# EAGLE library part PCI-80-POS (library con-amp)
PCI-SLOT 80 Dual Position 0.05 Series Standard Edge Source: http://catalog.tycoelectronics.com .. ENG_CD_650090_AA.tif.tiff
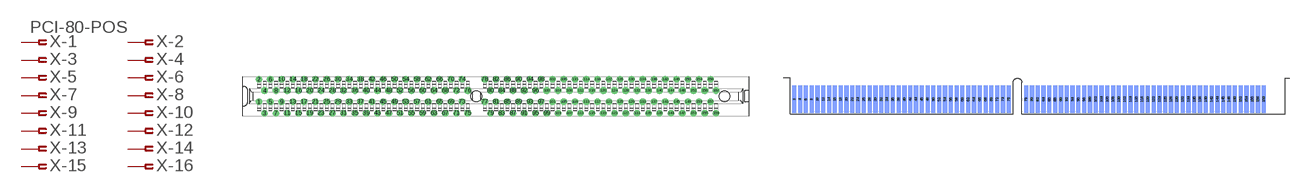
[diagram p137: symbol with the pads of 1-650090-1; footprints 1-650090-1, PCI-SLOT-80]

Designator prefix X; gates -1=PIN-FV -2=PIN-F -3=PIN-F -4=PIN-F -5=PIN-F -6=PIN-F -7=PIN-F -8=PIN-F -9=PIN-F -10=PIN-F -11=PIN-F -12=PIN-F -13=PIN-F -14=PIN-F -15=PIN-F -16=PIN-F -17=PIN-F -18=PIN-F -19=PIN-F -20=PIN-F -21=PIN-F -22=PIN-F -23=PIN-F -24=PIN-F -25=PIN-F -26=PIN-F -27=PIN-F -28=PIN-F -29=PIN-F -30=PIN-F -31=PIN-F -32=PIN-F -33=PIN-F -34=PIN-F -35=PIN-F -36=PIN-F -37=PIN-F -38=PIN-F -39=PIN-F -40=PIN-F -41=PIN-F -42=PIN-F -43=PIN-F -44=PIN-F -45=PIN-F -46=PIN-F -47=PIN-F -48=PIN-F -49=PIN-F -50=PIN-F -51=PIN-F -52=PIN-F -53=PIN-F -54=PIN-F -55=PIN-F -56=PIN-F -57=PIN-F -58=PIN-F -59=PIN-F -60=PIN-F -61=PIN-F -62=PIN-F -63=PIN-F -64=PIN-F -65=PIN-F -66=PIN-F -67=PIN-F -68=PIN-F -69=PIN-F -70=PIN-F -71=PIN-F -72=PIN-F -73=PIN-F -74=PIN-F -75=PIN-F -76=PIN-F -77=PIN-F -78=PIN-F -79=PIN-F -80=PIN-F -81=PIN-F -82=PIN-F -83=PIN-F -84=PIN-F -85=PIN-F -86=PIN-F -87=PIN-F -88=PIN-F -89=PIN-F -90=PIN-F -91=PIN-F -92=PIN-F -93=PIN-F -94=PIN-F -95=PIN-F -96=PIN-F -97=PIN-F -98=PIN-F -99=PIN-F -100=PIN-F -101=PIN-F -102=PIN-F -103=PIN-F -104=PIN-F -105=PIN-F -106=PIN-F -107=PIN-F -108=PIN-F -109=PIN-F -110=PIN-F -111=PIN-F -112=PIN-F -113=PIN-F -114=PIN-F -115=PIN-F -116=PIN-F -117=PIN-F -118=PIN-F -119=PIN-F -120=PIN-F -121=PIN-F -122=PIN-F -123=PIN-F -124=PIN-F -125=PIN-F -126=PIN-F -127=PIN-F -128=PIN-F -129=PIN-F -130=PIN-F -131=PIN-F -132=PIN-F -133=PIN-F -134=PIN-F -135=PIN-F -136=PIN-F -137=PIN-F -138=PIN-F -139=PIN-F -140=PIN-F -141=PIN-F -142=PIN-F -143=PIN-F -144=PIN-F -145=PIN-F -146=PIN-F -147=PIN-F -148=PIN-F -149=PIN-F -150=PIN-F -151=PIN-F -152=PIN-F -153=PIN-F -154=PIN-F -155=PIN-F -156=PIN-F -157=PIN-F -158=PIN-F -159=PIN-F -160=PIN-F

## PCI-80-POS-1-650090-1 (MF: TYCO ELECTRONICS; MPN: 1-650090-1; OC_FARNELL: unknown; OC_NEWARK: 10H3039)  [1-650090-1]
1  -1:1  pas
2  -2:1  pas
3  -3:1  pas
4  -4:1  pas
5  -5:1  pas
6  -6:1  pas
7  -7:1  pas
8  -8:1  pas
9  -9:1  pas
10  -10:1  pas
11  -11:1  pas
12  -12:1  pas
13  -13:1  pas
14  -14:1  pas
15  -15:1  pas
16  -16:1  pas
17  -17:1  pas
18  -18:1  pas
19  -19:1  pas
20  -20:1  pas
21  -21:1  pas
22  -22:1  pas
23  -23:1  pas
24  -24:1  pas
25  -25:1  pas
26  -26:1  pas
27  -27:1  pas
28  -28:1  pas
29  -29:1  pas
30  -30:1  pas
31  -31:1  pas
32  -32:1  pas
33  -33:1  pas
34  -34:1  pas
35  -35:1  pas
36  -36:1  pas
37  -37:1  pas
38  -38:1  pas
39  -39:1  pas
40  -40:1  pas
41  -41:1  pas
42  -42:1  pas
43  -43:1  pas
44  -44:1  pas
45  -45:1  pas
46  -46:1  pas
47  -47:1  pas
48  -48:1  pas
49  -49:1  pas
50  -50:1  pas
51  -51:1  pas
52  -52:1  pas
53  -53:1  pas
54  -54:1  pas
55  -55:1  pas
56  -56:1  pas
57  -57:1  pas
58  -58:1  pas
59  -59:1  pas
60  -60:1  pas
61  -61:1  pas
62  -62:1  pas
63  -63:1  pas
64  -64:1  pas
65  -65:1  pas
66  -66:1  pas
67  -67:1  pas
68  -68:1  pas
69  -69:1  pas
70  -70:1  pas
71  -71:1  pas
72  -72:1  pas
73  -73:1  pas
74  -74:1  pas
75  -75:1  pas
76  -76:1  pas
77  -77:1  pas
78  -78:1  pas
79  -79:1  pas
80  -80:1  pas
81  -81:1  pas
82  -82:1  pas
83  -83:1  pas
84  -84:1  pas
85  -85:1  pas
86  -86:1  pas
87  -87:1  pas
88  -88:1  pas
89  -89:1  pas
90  -90:1  pas
91  -91:1  pas
92  -92:1  pas
93  -93:1  pas
94  -94:1  pas
95  -95:1  pas
96  -96:1  pas
97  -97:1  pas
98  -98:1  pas
99  -99:1  pas
100  -100:1  pas
101  -101:1  pas
102  -102:1  pas
103  -103:1  pas
104  -104:1  pas
105  -105:1  pas
106  -106:1  pas
107  -107:1  pas
108  -108:1  pas
109  -109:1  pas
110  -110:1  pas
111  -111:1  pas
112  -112:1  pas
113  -113:1  pas
114  -114:1  pas
115  -115:1  pas
116  -116:1  pas
117  -117:1  pas
118  -118:1  pas
119  -119:1  pas
120  -120:1  pas
121  -121:1  pas
122  -122:1  pas
123  -123:1  pas
124  -124:1  pas
125  -125:1  pas
126  -126:1  pas
127  -127:1  pas
128  -128:1  pas
129  -129:1  pas
130  -130:1  pas
131  -131:1  pas
132  -132:1  pas
133  -133:1  pas
134  -134:1  pas
135  -135:1  pas
136  -136:1  pas
137  -137:1  pas
138  -138:1  pas
139  -139:1  pas
140  -140:1  pas
141  -141:1  pas
142  -142:1  pas
143  -143:1  pas
144  -144:1  pas
145  -145:1  pas
146  -146:1  pas
147  -147:1  pas
148  -148:1  pas
149  -149:1  pas
150  -150:1  pas
151  -151:1  pas
152  -152:1  pas
153  -153:1  pas
154  -154:1  pas
155  -155:1  pas
156  -156:1  pas
157  -157:1  pas
158  -158:1  pas
159  -159:1  pas
160  -160:1  pas

## PCI-80-POS-SLOT (OC_FARNELL: unknown; OC_NEWARK: unknown)  [PCI-SLOT-80]
Pads as for 1-650090-1

## Footprint 1-650090-1 (pad centres in mm)
PCI Connector 80 Dual Pos. Standard Edge .050 Series PCI Source: http://catalog.tycoelectronics.com .. ENG_CD_650090_AA.tif.tiff (ENG_SS_114-26012_O.pdf)
drill 1 pad 1.2 round: 1 0,-1.27; 2 0,3.81; 3 1.27,-3.81; 4 1.27,1.27; 5 2.54,-1.27; 6 2.54,3.81; 7 3.81,-3.81; 8 3.81,1.27; 9 5.08,-1.27; 10 5.08,3.81; 11 6.35,-3.81; 12 6.35,1.27; 13 7.62,-1.27; 14 7.62,3.81; 15 8.89,-3.81; 16 8.89,1.27; 17 10.16,-1.27; 18 10.16,3.81; 19 11.43,-3.81; 20 11.43,1.27; 21 12.7,-1.27; 22 12.7,3.81; 23 13.97,-3.81; 24 13.97,1.27; 25 15.24,-1.27; 26 15.24,3.81; 27 16.51,-3.81; 28 16.51,1.27; 29 17.78,-1.27; 30 17.78,3.81; 31 19.05,-3.81; 32 19.05,1.27; 33 20.32,-1.27; 34 20.32,3.81; 35 21.59,-3.81; 36 21.59,1.27; 37 22.86,-1.27; 38 22.86,3.81; 39 24.13,-3.81; 40 24.13,1.27; 41 25.4,-1.27; 42 25.4,3.81; 43 26.67,-3.81; 44 26.67,1.27; 45 27.94,-1.27; 46 27.94,3.81; 47 29.21,-3.81; 48 29.21,1.27; 49 30.48,-1.27; 50 30.48,3.81; 51 31.75,-3.81; 52 31.75,1.27; 53 33.02,-1.27; 54 33.02,3.81; 55 34.29,-3.81; 56 34.29,1.27; 57 35.56,-1.27; 58 35.56,3.81; 59 36.83,-3.81; 60 36.83,1.27; 61 38.1,-1.27; 62 38.1,3.81; 63 39.37,-3.81; 64 39.37,1.27; 65 40.64,-1.27; 66 40.64,3.81; 67 41.91,-3.81; 68 41.91,1.27; 69 43.18,-1.27; 70 43.18,3.81; 71 44.45,-3.81; 72 44.45,1.27; 73 45.72,-1.27; 74 45.72,3.81; 75 46.99,-3.81; 76 46.99,1.27; 77 50.8,-1.27; 78 50.8,3.81; 79 52.07,-3.81; 80 52.07,1.27; 81 53.34,-1.27; 82 53.34,3.81; 83 54.61,-3.81; 84 54.61,1.27; 85 55.88,-1.27; 86 55.88,3.81; 87 57.15,-3.81; 88 57.15,1.27; 89 58.42,-1.27; 90 58.42,3.81; 91 59.69,-3.81; 92 59.69,1.27; 93 60.96,-1.27; 94 60.96,3.81; 95 62.23,-3.81; 96 62.23,1.27; 97 63.5,-1.27; 98 63.5,3.81; 99 64.77,-3.81; 100 64.77,1.27; 101 66.04,-1.27; 102 66.04,3.81; 103 67.31,-3.81; 104 67.31,1.27; 105 68.58,-1.27; 106 68.58,3.81; 107 69.85,-3.81; 108 69.85,1.27; 109 71.12,-1.27; 110 71.12,3.81; 111 72.39,-3.81; 112 72.39,1.27; 113 73.66,-1.27; 114 73.66,3.81; 115 74.93,-3.81; 116 74.93,1.27; 117 76.2,-1.27; 118 76.2,3.81; 119 77.47,-3.81; 120 77.47,1.27; 121 78.74,-1.27; 122 78.74,3.81; 123 80.01,-3.81; 124 80.01,1.27; 125 81.28,-1.27; 126 81.28,3.81; 127 82.55,-3.81; 128 82.55,1.27; 129 83.82,-1.27; 130 83.82,3.81; 131 85.09,-3.81; 132 85.09,1.27; 133 86.36,-1.27; 134 86.36,3.81; 135 87.63,-3.81; 136 87.63,1.27; 137 88.9,-1.27; 138 88.9,3.81; 139 90.17,-3.81; 140 90.17,1.27; 141 91.44,-1.27; 142 91.44,3.81; 143 92.71,-3.81; 144 92.71,1.27; 145 93.98,-1.27; 146 93.98,3.81; 147 95.25,-3.81; 148 95.25,1.27; 149 96.52,-1.27; 150 96.52,3.81; 151 97.79,-3.81; 152 97.79,1.27; 153 99.06,-1.27; 154 99.06,3.81; 155 100.33,-3.81; 156 100.33,1.27; 157 101.6,-1.27; 158 101.6,3.81; 159 102.87,-3.81; 160 102.87,1.27
hole 2.44 at 48.89,0
hole 2.44 at 104.77,0

## Footprint PCI-SLOT-80 (pad centres in mm)
PCI Connector 80 Dual Pos. Standard Edge .050 Series PCI Source: http://catalog.tycoelectronics.com .. ENG_CD_650090_AA.tif.tiff
smd 0.91 x 6: 1 0,3.22; 3 1.27,3.22; 5 2.54,3.22; 7 3.81,3.22; 9 5.08,3.22; 11 6.35,3.22; 13 7.62,3.22; 15 8.89,3.22; 17 10.16,3.22; 19 11.43,3.22; 21 12.7,3.22; 23 13.97,3.22; 25 15.24,3.22; 27 16.51,3.22; 29 17.78,3.22; 31 19.05,3.22; 33 20.32,3.22; 35 21.59,3.22; 37 22.86,3.22; 39 24.13,3.22; 41 25.4,3.22; 43 26.67,3.22; 45 27.94,3.22; 47 29.21,3.22; 49 30.48,3.22; 51 31.75,3.22; 53 33.02,3.22; 55 34.29,3.22; 57 35.56,3.22; 59 36.83,3.22; 61 38.1,3.22; 63 39.37,3.22; 65 40.64,3.22; 67 41.91,3.22; 69 43.18,3.22; 71 44.45,3.22; 73 45.72,3.22; 75 46.99,3.22; 77 50.8,3.22; 79 52.07,3.22; 81 53.34,3.22; 83 54.61,3.22; 85 55.88,3.22; 87 57.15,3.22; 89 58.42,3.22; 91 59.69,3.22; 93 60.96,3.22; 95 62.23,3.22; 97 63.5,3.22; 99 64.77,3.22; 101 66.04,3.22; 103 67.31,3.22; 105 68.58,3.22; 107 69.85,3.22; 109 71.12,3.22; 111 72.39,3.22; 113 73.66,3.22; 115 74.93,3.22; 117 76.2,3.22; 119 77.47,3.22; 121 78.74,3.22; 123 80.01,3.22; 125 81.28,3.22; 127 82.55,3.22; 129 83.82,3.22; 131 85.09,3.22; 133 86.36,3.22; 135 87.63,3.22; 137 88.9,3.22; 139 90.17,3.22; 141 91.44,3.22; 143 92.71,3.22; 145 93.98,3.22; 147 95.25,3.22; 149 96.52,3.22; 151 97.79,3.22; 153 99.06,3.22; 155 100.33,3.22; 157 101.6,3.22; 159 102.87,3.22
smd 0.91 x 6 bottom: 2 0,3.22; 4 1.27,3.22; 6 2.54,3.22; 8 3.81,3.22; 10 5.08,3.22; 12 6.35,3.22; 14 7.62,3.22; 16 8.89,3.22; 18 10.16,3.22; 20 11.43,3.22; 22 12.7,3.22; 24 13.97,3.22; 26 15.24,3.22; 28 16.51,3.22; 30 17.78,3.22; 32 19.05,3.22; 34 20.32,3.22; 36 21.59,3.22; 38 22.86,3.22; 40 24.13,3.22; 42 25.4,3.22; 44 26.67,3.22; 46 27.94,3.22; 48 29.21,3.22; 50 30.48,3.22; 52 31.75,3.22; 54 33.02,3.22; 56 34.29,3.22; 58 35.56,3.22; 60 36.83,3.22; 62 38.1,3.22; 64 39.37,3.22; 66 40.64,3.22; 68 41.91,3.22; 70 43.18,3.22; 72 44.45,3.22; 74 45.72,3.22; 76 46.99,3.22; 78 50.8,3.22; 80 52.07,3.22; 82 53.34,3.22; 84 54.61,3.22; 86 55.88,3.22; 88 57.15,3.22; 90 58.42,3.22; 92 59.69,3.22; 94 60.96,3.22; 96 62.23,3.22; 98 63.5,3.22; 100 64.77,3.22; 102 66.04,3.22; 104 67.31,3.22; 106 68.58,3.22; 108 69.85,3.22; 110 71.12,3.22; 112 72.39,3.22; 114 73.66,3.22; 116 74.93,3.22; 118 76.2,3.22; 120 77.47,3.22; 122 78.74,3.22; 124 80.01,3.22; 126 81.28,3.22; 128 82.55,3.22; 130 83.82,3.22; 132 85.09,3.22; 134 86.36,3.22; 136 87.63,3.22; 138 88.9,3.22; 140 90.17,3.22; 142 91.44,3.22; 144 92.71,3.22; 146 93.98,3.22; 148 95.25,3.22; 150 96.52,3.22; 152 97.79,3.22; 154 99.06,3.22; 156 100.33,3.22; 158 101.6,3.22; 160 102.87,3.22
